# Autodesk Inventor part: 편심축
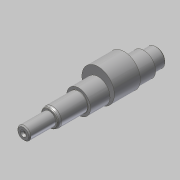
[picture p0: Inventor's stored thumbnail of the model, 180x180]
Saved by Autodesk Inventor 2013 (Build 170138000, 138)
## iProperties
Created: 2020-07
Part Number: 편심축
Material: 강철, 연강
Document SubType Name: Modeling
Designer: mduedu
Density: 7.86 g/cm^3
Mass: 329.439 g
Surface Area: 91.9337 cm^2
Volume: 41.9133 cm^3
Author: mduedu
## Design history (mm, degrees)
sketch "스케치1"
  geometry: L1 (0, 0)-(24, 0); L2 (24, 0)-(24, 6); L3 (24, 6)-(0, 6); L4 (0, 6)-(0, 0); L5 (24, 0)-(51, 0); L6 (51, 0)-(51, 8.5); L7 (51, 8.5)-(24, 8.5); L8 (24, 8.5)-(24, 0); L9 (51, 0)-(111, 0); L10 (111, 0)-(111, 11); L11 (111, 11)-(51, 11); L12 (51, 11)-(51, 0); L13 (111, 0)-(123, 0); L14 (123, 0)-(123, 8.5); L15 (123, 8.5)-(111, 8.5); L16 (111, 8.5)-(111, 0)
  constraints: 32 end point, 8 parallel, 4 horizontal, 4 perpendicular
  dimensions: "d0" = 123 distance between parallel lines of L14 L4; "d2" = 12 distance of L14.end L15.end; "d3" = 60 distance of L10.end L11.end; "d4" = 99 distance between parallel lines of L8 L14; "d5" = 24 distance of L2.end L3.end (derived); "d6" = 12 diameter of L3 L1; "d7" = 17 diameter of L7 L5; "d8" = 22 diameter of L11 L9; "d9" = 17 diameter of L15 L13
revolve "회전1" sketch "스케치1" stored, may be unused: angle "d10" = 90 deg
node "작업 평면1"
sketch "스케치2"
  geometry: C1 r 15 at (-4, 0); C2 r 11 at (0, 0) reference; 1 further point
  constraints: 1 centre point, 1 horizontal alignment, 1 tangent
  dimensions: "d12" = 4 distance of point (0, 0) C1.centre
extrude "돌출1" join sketch "스케치2" distance "d13" = 24; taper "d14" = 0 deg
node "작업 평면2"
sketch "스케치3" dims "d17" = 12
  geometry: L1 (5, -2)-(-3, -2); L2 (-3, -2)-(-3, 2); L3 (-3, 2)-(5, 2); L4 (5, 2)-(5, -2); L5 (-12, 8.5)-(-12, -8.5); L6 (-12, 8.5)-(-12, -8.5) reference; L7 (12, 6)-(12, -6) reference; 5 further points
  constraints: 10 end point, 4 midpoint, 2 horizontal alignment, 2 parallel, 2 vertical alignment, 1 coincident, 1 collinear, 1 horizontal, 1 perpendicular, 4 other
  dimensions: "d15" = 7 dimension on L5; "d16" = 4 distance between parallel lines of L3 L1
extrude "돌출2" cut sketch "스케치3" distance "d18" = 2.5; taper "d19" = 0 deg
hole "구멍1" diameter "d22" = 3.242; stored, may be unused: countersink angle "d26" = 90 deg, drill point angle "d28" = 118 deg; dims "d20" = 10, "d21" = 10, "d23" = 8, "d24" = 4, "d25" = 2, "d27" = 10
sketch "스케치4"
  geometry: L1 (10, 1.621)-(0, 1.621) reference; L2 (0, 0)-(2, 0); L3 (2, 0)-(2, 1.621); L4 (0, 2.776)-(0, 0); L5 (0, 2.776)-(2, 1.621)
  constraints: 8 end point, 1 horizontal, 1 parallel, 1 perpendicular, 1 point on line
  dimensions: "d29" = 2 horizontal distance of L4.start L3.end; "d31" = 30 deg angle of L5 L2
revolve "회전2" sketch "스케치4" stored, may be unused: angle "d33" = 90 deg
chamfer "모따기1" distance "d34" = 1; stored, may be unused: second distance "d35" = 2, angle "d36" = 45 deg
fillet "모깎기1" dims "d37" = 0.3
sketch "스케치5"
  geometry: L1 (24, -8.5)-(24, 8.5) reference; L2 (24, 8.5)-(50.7, 8.5) reference; L3 (24, 7.45)-(25.819, 8.5); L4 (0, 0)-(24, 0)
  constraints: 4 end point, 2 point on line, 1 midpoint
  dimensions: "d38" = 14.9 diameter of L3.start L4; "d39" = 30 deg angle of L3 L2
revolve "회전3" sketch "스케치5" stored, may be unused: angle "d40" = 90 deg
fillet "모깎기2" dims "d41" = 4, "d42" = 0.5
node "솔리드1"
